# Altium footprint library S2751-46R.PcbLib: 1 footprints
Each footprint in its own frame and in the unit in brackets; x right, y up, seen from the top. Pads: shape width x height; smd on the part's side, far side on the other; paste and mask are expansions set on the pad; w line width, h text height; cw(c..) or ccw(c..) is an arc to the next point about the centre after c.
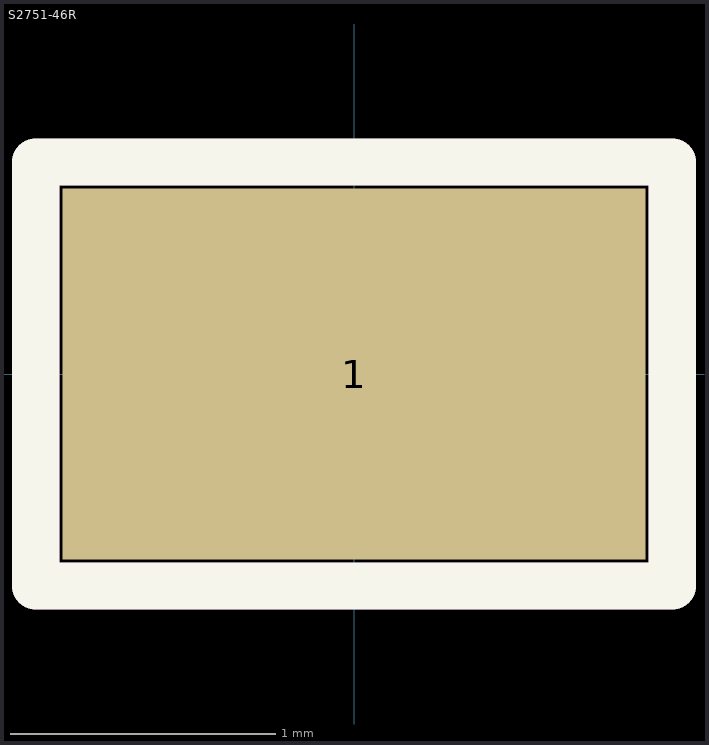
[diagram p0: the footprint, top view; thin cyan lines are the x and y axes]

## S2751-46R [mm] "Harwin P/N S2751-46R"
height 1.15
pads (1):
  rect 2.2x1.4 smd: 1(0,0)
Top Overlay:
  lines w0.178: -1.2,-0.8 -1.2,0.8 1.2,0.8 1.2,-0.8 -1.2,-0.8
M5 Assembly Top:
  lines w0.178: -1.2,-0.8 1.2,-0.8 1.2,0.8 -1.2,0.8 -1.2,-0.8
  text ".Designator" at -2.3,-0.2 h1
3D body "s2751-46r.stp": height 1.41, standoff -0.01, extent -1,-0.6 1,0.6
